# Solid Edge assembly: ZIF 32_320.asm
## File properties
Title: Zylinder
Author: bmolnar
Template: iso metric assembly.asm
Last saved by: psaghy
Revision: 35
Application: Solid Edge
Username: bmolnar
Dokumentum tartalom típus: 1
Document Number: ZIF 32/320
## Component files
Kit_1.par
Kit_2.par
Profilrohr.par
Kolbenstange.par
Mutter.par
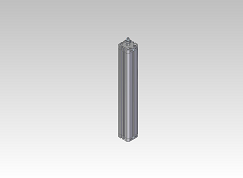
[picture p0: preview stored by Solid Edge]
